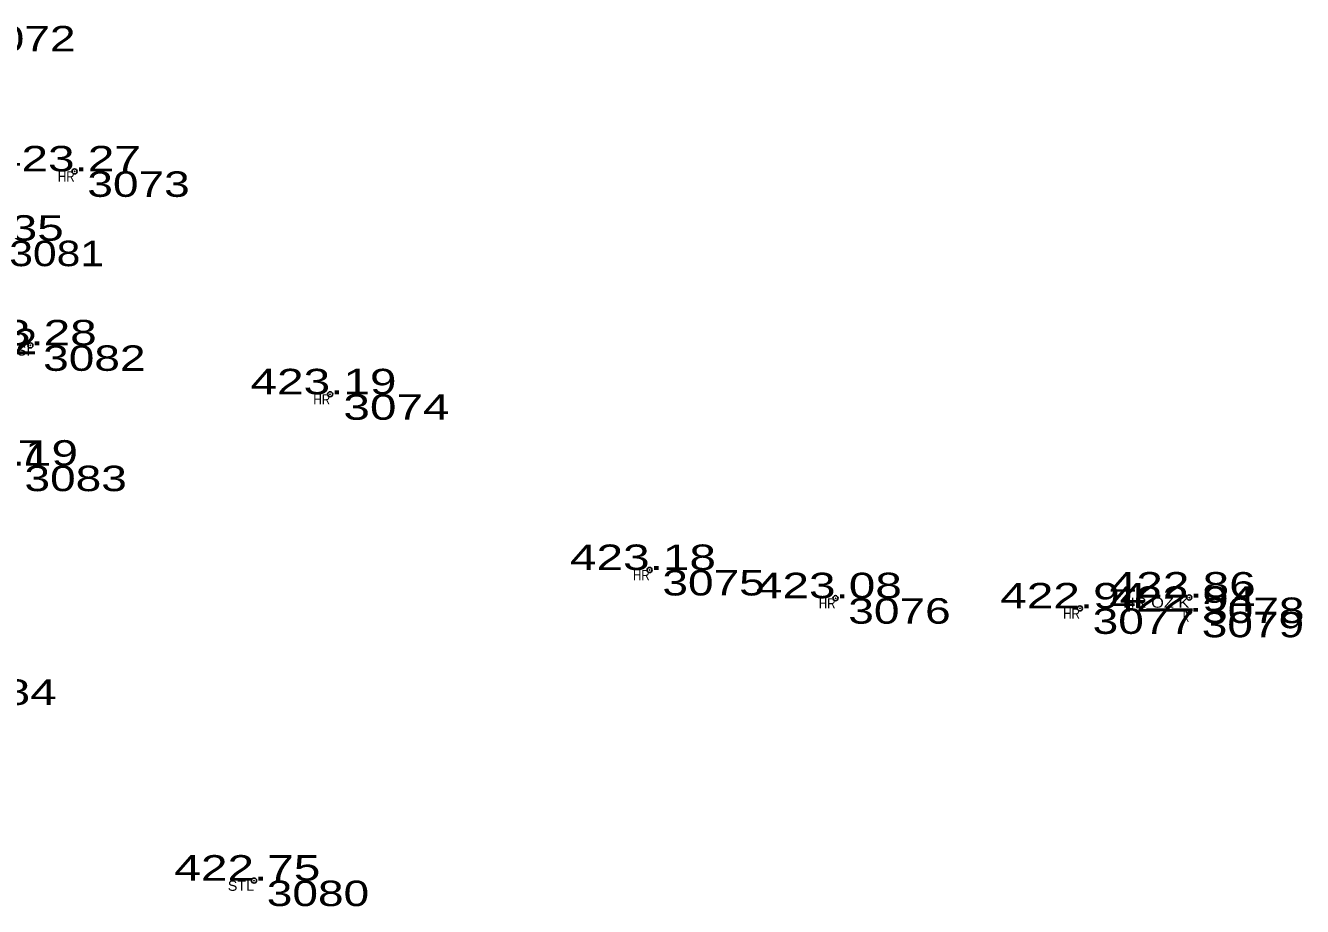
# Model space of a CAD drawing. Extents: x -639390 to -639074, y -1138747 to -1138358.
# Drawn here: x -639126.7 to -639089.13, y -1138616.47 to -1138590.55 of the extents above; entities that cross this region are included whole.
import ezdxf
from ezdxf.enums import TextEntityAlignment as Align

# ---------------------------------------------------------------- set-up
doc = ezdxf.new("R2010")
doc.units = 0
doc.header["$LTSCALE"] = 0.3
doc.header["$PDMODE"] = 32
doc.header["$PDSIZE"] = 0.15
for name, color, linetype in [('11', 7, 'Continuous'), ('12', 7, 'Continuous'), ('13', 7, 'Continuous'), ('57', 7, 'Continuous')]:
    doc.layers.add(name, color=color, linetype=linetype)

msp = doc.modelspace()

# ---------------------------------------------------------------- linework, layer by layer
at = {"layer": '11'}
for p in [(-639125.26, -1138594.84), (-639126.56, -1138599.96), (-639117.74, -1138601.4), (-639108.34, -1138606.57), (-639102.87, -1138607.4), (-639092.46, -1138607.38), (-639095.68, -1138607.7), (-639092.47, -1138607.8), (-639119.98, -1138615.71)]:
    msp.add_point(p, dxfattribs=at)

# ---------------------------------------------------------------- texts
at = {"layer": '12', "width": 1.4}
for s, p in [('423.27 ', (-639125.26, -1138594.84)), ('423.35 ', (-639127.53, -1138596.88)), ('423.28 ', (-639126.56, -1138599.96)), ('423.19 ', (-639117.74, -1138601.4)), ('423.19 ', (-639127.11, -1138603.5)), ('423.18 ', (-639108.34, -1138606.57)), ('423.08 ', (-639102.87, -1138607.4)), ('422.86 ', (-639092.459, -1138607.38)), ('422.94 ', (-639095.68, -1138607.7)), ('422.94 ', (-639092.47, -1138607.8)), ('422.75 ', (-639119.98, -1138615.71))]:
    msp.add_text(s, height=0.75, dxfattribs=at).set_placement(p, align=Align.CENTER)
at = {"layer": '13'}
for s, width, p in [(' 3072', 1.35, (-639128.62, -1138591.31)), (' 3073', 1.35, (-639125.26, -1138595.59)), (' 3081', 1.25, (-639127.53, -1138597.63)), (' 3102', 1.25, (-639129.5, -1138600.22)), (' 3082', 1.35, (-639126.56, -1138600.71)), (' 3074', 1.4, (-639117.74, -1138602.15)), (' 3097', 1.35, (-639129.57, -1138603.5)), (' 3083', 1.35, (-639127.11, -1138604.25)), (' 3075', 1.35, (-639108.34, -1138607.32)), (' 3076', 1.35, (-639102.87, -1138608.15)), (' 3078', 1.35, (-639092.46, -1138608.13)), (' 3077', 1.35, (-639095.68, -1138608.45)), (' 3079', 1.35, (-639092.47, -1138608.55)), (' 3084', 1.4, (-639129.3, -1138610.54)), (' 3080', 1.35, (-639119.98, -1138616.46))]:
    msp.add_text(s, height=0.75, dxfattribs=dict(at, width=width)).set_placement(p)
at = {"layer": '57'}
for s, width, p in [('HR', 0.85, (-639125.259, -1138595.14)), ('SI', 1.05, (-639126.56, -1138600.26)), ('HR', 0.85, (-639117.739, -1138601.7)), ('HR', 0.85, (-639108.339, -1138606.87)), ('HR', 0.85, (-639102.869, -1138607.7)), ('HR OZ K', 1.2, (-639092.459, -1138607.68)), ('HR', 0.85, (-639095.679, -1138608)), ('K', 0.65, (-639092.469, -1138608.1)), ('STL', 1.05, (-639119.979, -1138616.01))]:
    msp.add_text(s, height=0.3, dxfattribs=dict(at, width=width)).set_placement(p, align=Align.RIGHT)

doc.saveas('drawing.dxf')
